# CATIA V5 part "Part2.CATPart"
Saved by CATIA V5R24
Part number: Support2
Bounding box of the stored display mesh (mm): x 0 to 20, y -94.473 to 105.527, z -30 to 0
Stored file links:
  G:\_CAD수업\DMU_paradoxes\2\Part2.CATPart
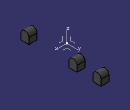
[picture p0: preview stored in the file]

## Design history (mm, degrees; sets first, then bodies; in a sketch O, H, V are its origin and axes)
AxisSystem1: origin (0, 0, 0), X (1, 0, 0), Y (0, 1, 0), Z (0, 0, 1)
Body1 (main body)
  Sketch1 on YZ plane of AxisSystem1, origin (0, 0, 0), H (0, 1, 0), V (0, 0, 1)
    line L1 (-94.4731, -5) -> (-74.4731, -5)
    line L2 (-74.4731, -5) -> (-74.4731, -30)
    line L3 (-74.4731, -30) -> (-94.4731, -30)
    line L4 (-94.4731, -30) -> (-94.4731, -5)
    line L5 (25.5269, -5) -> (45.5269, -5)
    line L6 (45.5269, -5) -> (45.5269, -30)
    line L7 (45.5269, -30) -> (25.5269, -30)
    line L8 (25.5269, -30) -> (25.5269, -5)
    line L9 (85.5269, -5) -> (105.5269, -5)
    line L10 (105.5269, -5) -> (105.5269, -30)
    line L11 (105.5269, -30) -> (85.5269, -30)
    line L12 (85.5269, -30) -> (85.5269, -5)
    length L11 = 20
    length L7 = 20
    length L3 = 20
    distance L8 L4 = 120
    distance L12 L8 = 60
    length L10 = 25
    length L6 = 25
    length L2 = 25
    horizontal: L1 H, L3 H, L5 H, L7 H, L9 H, L11 H
    vertical: L2 V, L4 V, L6 V, L8 V, L10 V, L12 V
    coincidence: L11 L7, L7 L3
  Pad1: profile Sketch1, direction (1, 0, 0), length 20
  TritangentFillet1: Face1 face of Pad1 from Sketch1.L4, Face2 face of Pad1 from Sketch1.L2, RemoveFace face of Pad1 from Sketch1.L1
  TritangentFillet2: Face1 face of Pad1 from Sketch1.L6, Face2 face of Pad1 from Sketch1.L8, RemoveFace face of Pad1 from Sketch1.L5
  TritangentFillet3: Face1 face of Pad1 from Sketch1.L12, Face2 face of Pad1 from Sketch1.L10, RemoveFace face of Pad1 from Sketch1.L9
